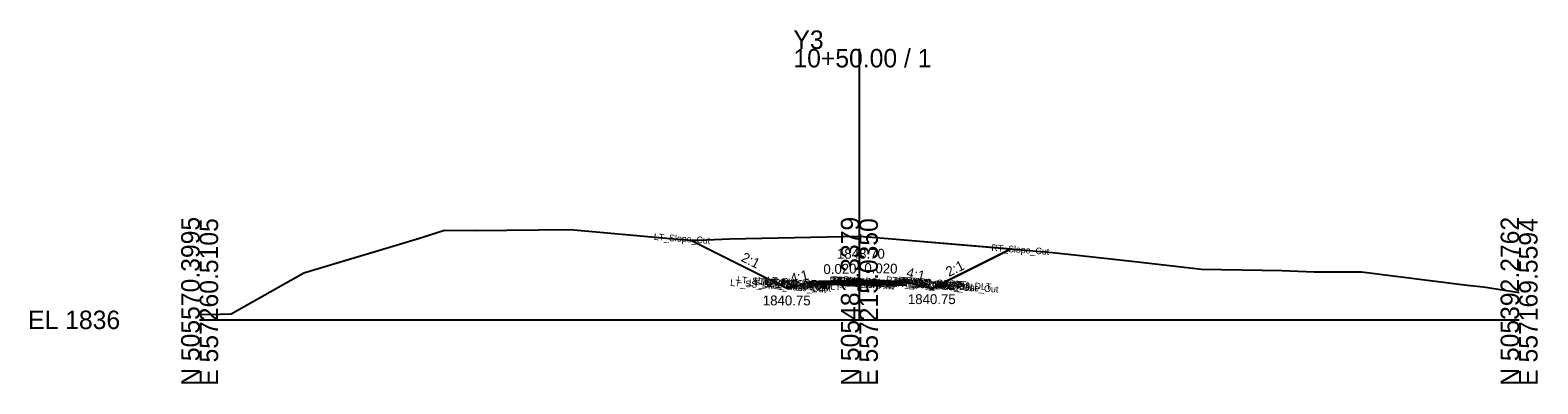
# Model space of a CAD drawing. Extents: x -26 to 1503, y -10 to 2064.
# Drawn here: x -25.7 to 202.8, y 490.3 to 543.9 of the extents above; entities that cross this region are included whole.
import ezdxf

# ---------------------------------------------------------------- set-up
doc = ezdxf.new("R2010")
doc.units = 0
for name, color, linetype in [('Default', 7, 'Continuous'), ('Exist Cross Section Cell', 7, 'Continuous'), ('Exist XS Center Line Elevation Label', 7, 'Continuous'), ('Exist XS Ground Line', 7, 'Continuous'), ('Prop CMT Pvmt Course 1', 7, 'Continuous'), ('Prop CMT Pvmt Course 2', 7, 'Continuous'), ('Prop CMT Pvmt Surface', 7, 'Continuous'), ('Prop CMT Shld Paved Course 1', 7, 'Continuous'), ('Prop CMT Shld Paved Course 2', 7, 'Continuous'), ('Prop CMT Slope Grass', 7, 'Continuous'), ('Prop CMT Subgrade Earthwork', 7, 'Continuous'), ('Prop XS Ditch Standard Text', 7, 'Continuous'), ('Prop XS Earthwork Shape', 7, 'Continuous'), ('Prop XS SE Text', 7, 'Continuous'), ('Prop XS Side Slope Text', 7, 'Continuous'), ('Typical Text General CELL', 7, 'Continuous')]:
    doc.layers.add(name, color=color, linetype=linetype)

msp = doc.modelspace()

# ---------------------------------------------------------------- linework, layer by layer
at = {"layer": 'Exist Cross Section Cell'}
for p, q in [((100, 500), (100, 541.05)), ((0, 500), (100, 500)), ((100, 500), (200, 500))]:
    msp.add_line(p, q, dxfattribs=at)
at = {"layer": 'Exist XS Ground Line'}
for p, q in [((15.77, 507.14), (33.3, 512.37)), ((33.3, 512.37), (37.11, 513.6)), ((37.11, 513.6), (41.74, 513.53)), ((41.74, 513.53), (56.15, 513.68)), ((56.15, 513.68), (72.44, 512.23)), ((72.44, 512.23), (74.54, 512.07)), ((74.54, 512.07), (75.68, 512.05)), ((75.68, 512.05), (80.33, 512.26)), ((80.33, 512.26), (100, 512.7)), ((100, 512.7), (104.99, 512.26)), ((104.99, 512.26), (129.29, 510.23)), ((129.29, 510.23), (133.06, 509.81)), ((133.06, 509.81), (141.77, 508.86)), ((141.77, 508.86), (151.88, 507.7)), ((151.88, 507.7), (164.04, 507.48)), ((164.04, 507.48), (168.95, 507.3)), ((4.79, 500.9), (15.77, 507.14)), ((168.95, 507.3), (176.12, 507.28)), ((176.12, 507.28), (192.15, 505.24)), ((192.15, 505.24), (194.59, 505.01)), ((194.59, 505.01), (200, 504.14)), ((0, 500.83), (3.13, 500.88)), ((3.13, 500.88), (4.79, 500.9))]:
    msp.add_line(p, q, dxfattribs=at)
at = {"layer": 'Prop CMT Pvmt Course 1'}
for points in [[(100.12, 505.95), (94, 505.83)], [(94, 505.83), (94, 505.58)], [(94, 505.58), (100.12, 505.7)], [(100.12, 505.7), (100.12, 505.95)], [(100.12, 505.95), (106, 505.83)], [(100.12, 505.7), (100.12, 505.95)], [(106, 505.58), (100.12, 505.7)], [(106, 505.83), (106, 505.58)]]:
    msp.add_lwpolyline(points, dxfattribs=at)
msp.add_lwpolyline([(100.12, 505.7), (100.12, 505.82), (100.12, 505.82), (100.12, 505.7)], close=True, dxfattribs=at)
msp.add_lwpolyline([(100.12, 505.7), (100.12, 505.82), (100.12, 505.82), (100.12, 505.7)], close=True, dxfattribs=at)
at = {"layer": 'Prop CMT Pvmt Course 2'}
for points in [[(100.12, 505.7), (94, 505.58)], [(94, 505.58), (94, 505.33)], [(94, 505.33), (100.12, 505.45)], [(100.12, 505.45), (100.12, 505.7)], [(100.12, 505.45), (100.12, 505.7)], [(100.12, 505.7), (106, 505.58)], [(106, 505.33), (100.12, 505.45)], [(106, 505.58), (106, 505.33)]]:
    msp.add_lwpolyline(points, dxfattribs=at)
at = {"layer": 'Prop CMT Pvmt Surface'}
for points in [[(100.12, 505.95), (94, 505.83)], [(100.12, 505.95), (106, 505.83)]]:
    msp.add_lwpolyline(points, dxfattribs=at)
at = {"layer": 'Prop CMT Shld Paved Course 1'}
msp.add_line((93.75, 505.57), (94, 505.58), dxfattribs=at)
for points in [[(94, 505.83), (93.75, 505.57)], [(106, 505.83), (106.25, 505.58)], [(106, 505.58), (106, 505.83)], [(106.25, 505.58), (106, 505.58)]]:
    msp.add_lwpolyline(points, dxfattribs=at)
at = {"layer": 'Prop CMT Shld Paved Course 2'}
for points in [[(94.25, 505.58), (94, 505.58), (93.5, 505.57), (93.26, 505.32)], [(106, 505.58), (106.25, 505.58), (106.75, 505.57), (107, 505.32)], [(106, 505.33), (106, 505.58)], [(107, 505.32), (106, 505.33)]]:
    msp.add_lwpolyline(points, dxfattribs=at)
at = {"layer": 'Prop CMT Slope Grass'}
for points in [[(89.01, 504.75), (74.33, 512.09)], [(111, 504.75), (123, 510.75)], [(94, 505.83), (93, 505.75), (89.01, 504.75)], [(106, 505.83), (107, 505.75), (111, 504.75)]]:
    msp.add_lwpolyline(points, dxfattribs=at)
at = {"layer": 'Prop CMT Subgrade Earthwork'}
for points in [[(94, 505.33), (93, 505.32), (92.66, 505.66)], [(100.12, 505.45), (94, 505.33)], [(100.12, 505.45), (106, 505.33)], [(106, 505.33), (107, 505.32), (107.34, 505.67)]]:
    msp.add_lwpolyline(points, dxfattribs=at)
at = {"layer": 'Prop XS Earthwork Shape'}
for points in [[(100, 512.7), (104.99, 512.26), (123, 510.75), (111, 504.75), (107.34, 505.67), (107, 505.75), (106, 505.83), (100.12, 505.95), (94, 505.83), (93, 505.75), (92.66, 505.66), (89.01, 504.75), (74.33, 512.09), (74.54, 512.07), (75.68, 512.05), (80.33, 512.26)], [(107, 505.75), (107.34, 505.67), (107, 505.32), (106, 505.33), (100.12, 505.45), (94, 505.33), (93, 505.32), (92.66, 505.66), (93, 505.75), (94, 505.83), (100.12, 505.95), (106, 505.83)]]:
    msp.add_lwpolyline(points, close=True, dxfattribs=at)

# ---------------------------------------------------------------- texts
at = {"layer": 'Default'}
msp.add_text('-', height=0.0001, dxfattribs=at).set_placement((0, 500))
at = {"layer": 'Exist Cross Section Cell'}
for s, p in [('Y3', (90, 541.05)), ('10+50.00 / 1', (90, 538.25)), ('EL 1836', (-26, 498.6))]:
    msp.add_text(s, height=2.8, dxfattribs=at).set_placement(p)
for s, p in [('N 505570.3995', (0, 490)), ('E 557260.5105', (2.8, 490)), ('N 505481.3379', (100, 490)), ('E 557215.0350', (102.8, 490)), ('N 505392.2762', (200, 490)), ('E 557169.5594', (202.8, 490))]:
    msp.add_text(s, height=2.8, rotation=90, dxfattribs=at).set_placement(p)
at = {"layer": 'Exist XS Center Line Elevation Label'}
msp.add_text('1848.70', height=1.5, dxfattribs=at).set_placement((96.6, 509.27))
at = {"layer": 'Prop XS Ditch Standard Text'}
for p in [(85.36, 502.19), (107.35, 502.39)]:
    msp.add_text('1840.75', height=1.5, dxfattribs=at).set_placement(p)
at = {"layer": 'Prop XS SE Text'}
for rotation, p in [(1.1484, (94.56, 506.92)), (358.8516, (100.74, 507.1))]:
    msp.add_text('0.020', height=1.5, rotation=rotation, dxfattribs=at).set_placement(p)
at = {"layer": 'Prop XS Side Slope Text'}
for s, rotation, p in [('2:1', 333.4209, (81.95, 508.96)), ('4:1', 14.0678, (89.71, 505.47)), ('4:1', 345.9322, (107.02, 506.52)), ('2:1', 26.572, (113.57, 506.49))]:
    msp.add_text(s, height=1.5, rotation=rotation, dxfattribs=at).set_placement(p)
at = {"layer": 'Typical Text General CELL'}
for s, p in [('LT_Slope_Cut', (68.82, 512.11)), ('RT_Slope_Cut', (119.99, 510.45)), ('LT_SS_Ditch_Base_Out', (80.39, 505.14)), ('LT_Sub_Trench_Out_DLT', (81.43, 505.6)), ('LT_Sub_Trench_Out', (83.23, 505.15)), ('LT_PS2_Shelf_Out', (84.02, 505.36)), ('LT_GS_OS_CTL', (84.58, 505.49)), ('LT_PS2_OEOP', (85.65, 505.29)), ('LT_PV2_OEOT', (85.86, 505.3)), ('LT_Sub_OEOT', (85.88, 505.05)), ('LT_PV1_OEOT', (85.98, 505.54)), ('RT_PV2_OEEOP', (95.43, 505.53)), ('RT_Sub_OEEOP', (95.45, 505.27)), ('LT_PV2_OEEOP', (95.49, 505.52)), ('LT_Sub_OEEOP', (95.51, 505.27)), ('RT_PV1_OEEOP', (95.55, 505.64)), ('LT_PV1_OEEOP', (95.61, 505.64)), ('RT_PV2_IEEOP', (95.81, 505.5)), ('LT_PV2_IEEOP', (95.87, 505.5)), ('RT_PV1_IEEOP', (95.93, 505.62)), ('LT_PV1_IEEOP', (95.98, 505.61)), ('PV2_PGL', (97.44, 505.39)), ('PV1_PGL', (97.56, 505.63)), ('RT_Sub_Trench_Out_DLT', (104.01, 505.6)), ('RT_Sub_Trench_Out', (105.12, 505.16)), ('RT_PS2_Shelf_Out', (105.42, 505.36)), ('RT_PV2_OEOT', (105.76, 505.3)), ('RT_Sub_OEOT', (105.78, 505.05)), ('RT_PV1_OEOT', (105.87, 505.54)), ('RT_PS2_OEOP', (106.05, 505.29)), ('RT_SS_Ditch_Base_Out', (106.27, 505.15)), ('RT_GS_OS_CTL', (106.47, 505.49))]:
    msp.add_text(s, height=1, rotation=356, dxfattribs=at).set_placement(p)

doc.saveas('drawing.dxf')
